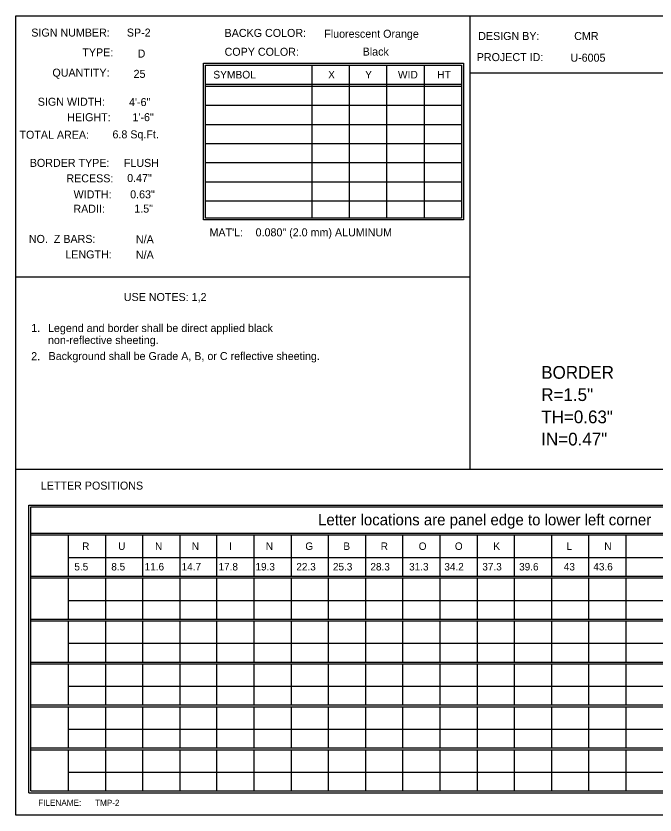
# Model space of a CAD drawing. Extents: x 766449 to 768137, y 650958 to 652521.
# Drawn here: x 767381.7 to 767770.1, y 651768.8 to 652254.2 of the extents above; entities that cross this region are included whole.
import ezdxf

# ---------------------------------------------------------------- set-up
doc = ezdxf.new("R2010")
doc.units = 0
doc.layers.add('Old_Level_3', color=7, linetype='Continuous')
doc.layers.add('Text', color=7, linetype='Continuous')

msp = doc.modelspace()

# ---------------------------------------------------------------- linework, layer by layer
at = {"layer": 'Text'}
for p, q in [((767657.51, 652254.24), (767657.51, 651978.93)), ((767561.46, 652224.37), (767561.46, 652131.49)), ((767584.2, 652224.37), (767584.2, 652131.49)), ((767606.95, 652224.37), (767606.95, 652131.49)), ((767629.69, 652224.37), (767629.69, 652131.49)), ((767657.51, 652219.7), (768081.66, 652219.7)), ((767496.83, 652212.76), (767652.43, 652212.76)), ((767496.83, 652211.61), (767652.43, 652211.61)), ((767496.83, 652200), (767652.43, 652200)), ((767496.83, 652188.39), (767652.43, 652188.39)), ((767496.83, 652176.78), (767652.43, 652176.78)), ((767496.83, 652165.17), (767652.43, 652165.17)), ((767496.83, 652153.56), (767652.43, 652153.56)), ((767496.83, 652141.95), (767652.43, 652141.95)), ((767657.51, 652095.65), (767381.66, 652095.65)), ((767381.66, 651978.93), (767657.51, 651978.93)), ((767657.51, 651978.93), (768081.66, 651978.93)), ((767390.64, 651940.06), (767928.82, 651940.06)), ((767390.64, 651938.93), (767928.82, 651938.93)), ((767413.33, 651938.93), (767413.33, 651913.95)), ((767436.02, 651938.93), (767436.02, 651913.95)), ((767458.48, 651938.93), (767458.48, 651913.95)), ((767481.18, 651938.93), (767481.18, 651913.95)), ((767503.64, 651938.93), (767503.64, 651913.95)), ((767526.33, 651938.93), (767526.33, 651913.95)), ((767549.02, 651938.93), (767549.02, 651913.95)), ((767571.48, 651938.93), (767571.48, 651913.95)), ((767594.18, 651938.93), (767594.18, 651913.95)), ((767616.64, 651938.93), (767616.64, 651913.95)), ((767639.33, 651938.93), (767639.33, 651913.95)), ((767662.02, 651938.93), (767662.02, 651913.95)), ((767684.48, 651938.93), (767684.48, 651913.95)), ((767707.18, 651938.93), (767707.18, 651913.95)), ((767729.64, 651938.93), (767729.64, 651913.95)), ((767752.33, 651938.93), (767752.33, 651913.95)), ((767413.33, 651925.3), (767928.82, 651925.3)), ((767390.64, 651913.95), (767928.82, 651913.95)), ((767390.64, 651912.82), (767928.82, 651912.82)), ((767413.33, 651912.82), (767413.33, 651887.85)), ((767436.02, 651912.82), (767436.02, 651887.85)), ((767458.48, 651912.82), (767458.48, 651887.85)), ((767481.18, 651912.82), (767481.18, 651887.85)), ((767503.64, 651912.82), (767503.64, 651887.85)), ((767526.33, 651912.82), (767526.33, 651887.85)), ((767549.02, 651912.82), (767549.02, 651887.85)), ((767571.48, 651912.82), (767571.48, 651887.85)), ((767594.18, 651912.82), (767594.18, 651887.85)), ((767616.64, 651912.82), (767616.64, 651887.85)), ((767639.33, 651912.82), (767639.33, 651887.85)), ((767662.02, 651912.82), (767662.02, 651887.85)), ((767684.48, 651912.82), (767684.48, 651887.85)), ((767707.18, 651912.82), (767707.18, 651887.85)), ((767729.64, 651912.82), (767729.64, 651887.85)), ((767752.33, 651912.82), (767752.33, 651887.85)), ((767413.33, 651899.2), (767928.82, 651899.2)), ((767390.64, 651887.85), (767928.82, 651887.85)), ((767390.64, 651886.71), (767928.82, 651886.71)), ((767413.33, 651886.71), (767413.33, 651861.74)), ((767436.02, 651886.71), (767436.02, 651861.74)), ((767458.48, 651886.71), (767458.48, 651861.74)), ((767481.18, 651886.71), (767481.18, 651861.74)), ((767503.64, 651886.71), (767503.64, 651861.74)), ((767526.33, 651886.71), (767526.33, 651861.74)), ((767549.02, 651886.71), (767549.02, 651861.74)), ((767571.48, 651886.71), (767571.48, 651861.74)), ((767594.18, 651886.71), (767594.18, 651861.74)), ((767616.64, 651886.71), (767616.64, 651861.74)), ((767639.33, 651886.71), (767639.33, 651861.74)), ((767662.02, 651886.71), (767662.02, 651861.74)), ((767684.48, 651886.71), (767684.48, 651861.74)), ((767707.18, 651886.71), (767707.18, 651861.74)), ((767729.64, 651886.71), (767729.64, 651861.74)), ((767752.33, 651886.71), (767752.33, 651861.74)), ((767413.33, 651873.09), (767928.82, 651873.09)), ((767390.64, 651861.74), (767928.82, 651861.74)), ((767390.64, 651860.61), (767928.82, 651860.61)), ((767413.33, 651860.61), (767413.33, 651835.63)), ((767436.02, 651860.61), (767436.02, 651835.63)), ((767458.48, 651860.61), (767458.48, 651835.63)), ((767481.18, 651860.61), (767481.18, 651835.63)), ((767503.64, 651860.61), (767503.64, 651835.63)), ((767526.33, 651860.61), (767526.33, 651835.63)), ((767549.02, 651860.61), (767549.02, 651835.63)), ((767571.48, 651860.61), (767571.48, 651835.63)), ((767594.18, 651860.61), (767594.18, 651835.63)), ((767616.64, 651860.61), (767616.64, 651835.63)), ((767639.33, 651860.61), (767639.33, 651835.63)), ((767662.02, 651860.61), (767662.02, 651835.63)), ((767684.48, 651860.61), (767684.48, 651835.63)), ((767707.18, 651860.61), (767707.18, 651835.63)), ((767729.64, 651860.61), (767729.64, 651835.63)), ((767752.33, 651860.61), (767752.33, 651835.63)), ((767413.33, 651846.98), (767928.82, 651846.98)), ((767413.33, 651838.54), (767413.33, 651835.63)), ((767436.02, 651838.54), (767436.02, 651835.63)), ((767458.48, 651838.54), (767458.48, 651835.63)), ((767481.18, 651838.54), (767481.18, 651835.63)), ((767503.64, 651838.54), (767503.64, 651835.63)), ((767526.33, 651838.54), (767526.33, 651835.63)), ((767549.02, 651838.54), (767549.02, 651835.63)), ((767571.48, 651838.54), (767571.48, 651835.63)), ((767594.18, 651838.54), (767594.18, 651835.63)), ((767616.64, 651838.54), (767616.64, 651835.63)), ((767639.33, 651838.54), (767639.33, 651835.63)), ((767662.02, 651838.54), (767662.02, 651835.63)), ((767684.48, 651838.54), (767684.48, 651835.63)), ((767707.18, 651838.54), (767707.18, 651835.63)), ((767729.64, 651838.54), (767729.64, 651835.63)), ((767752.33, 651838.54), (767752.33, 651835.63)), ((767390.64, 651835.63), (767928.82, 651835.63)), ((767390.64, 651835.63), (767928.82, 651835.63)), ((767390.64, 651834.5), (767928.82, 651834.5)), ((767390.64, 651834.5), (767928.82, 651834.5)), ((767413.33, 651834.5), (767413.33, 651811.16)), ((767413.33, 651834.5), (767413.33, 651809.53)), ((767436.02, 651834.5), (767436.02, 651811.16)), ((767436.02, 651834.5), (767436.02, 651809.53)), ((767458.48, 651834.5), (767458.48, 651811.16)), ((767458.48, 651834.5), (767458.48, 651809.53)), ((767481.18, 651834.5), (767481.18, 651811.16)), ((767481.18, 651834.5), (767481.18, 651809.53)), ((767503.64, 651834.5), (767503.64, 651811.16)), ((767503.64, 651834.5), (767503.64, 651809.53)), ((767526.33, 651834.5), (767526.33, 651811.16)), ((767526.33, 651834.5), (767526.33, 651809.53)), ((767549.02, 651834.5), (767549.02, 651811.16)), ((767549.02, 651834.5), (767549.02, 651809.53)), ((767571.48, 651834.5), (767571.48, 651811.16)), ((767571.48, 651834.5), (767571.48, 651809.53)), ((767594.18, 651834.5), (767594.18, 651811.16)), ((767594.18, 651834.5), (767594.18, 651809.53)), ((767616.64, 651834.5), (767616.64, 651811.16)), ((767616.64, 651834.5), (767616.64, 651809.53)), ((767639.33, 651834.5), (767639.33, 651811.16)), ((767639.33, 651834.5), (767639.33, 651809.53)), ((767662.02, 651834.5), (767662.02, 651811.16)), ((767662.02, 651834.5), (767662.02, 651809.53)), ((767684.48, 651834.5), (767684.48, 651811.16)), ((767684.48, 651834.5), (767684.48, 651809.53)), ((767707.18, 651834.5), (767707.18, 651811.16)), ((767707.18, 651834.5), (767707.18, 651809.53)), ((767729.64, 651834.5), (767729.64, 651811.16)), ((767729.64, 651834.5), (767729.64, 651809.53)), ((767752.33, 651834.5), (767752.33, 651811.16)), ((767752.33, 651834.5), (767752.33, 651809.53)), ((767413.33, 651820.88), (767928.82, 651820.88)), ((767413.33, 651820.88), (767928.82, 651820.88)), ((767390.64, 651809.53), (767928.82, 651809.53)), ((767390.64, 651809.53), (767928.82, 651809.53)), ((767390.64, 651808.39), (767928.82, 651808.39)), ((767390.64, 651808.39), (767928.82, 651808.39)), ((767413.33, 651812.43), (767413.33, 651809.53)), ((767413.33, 651808.39), (767413.33, 651783.42)), ((767413.33, 651808.39), (767413.33, 651783.42)), ((767436.02, 651812.43), (767436.02, 651809.53)), ((767436.02, 651808.39), (767436.02, 651783.42)), ((767436.02, 651808.39), (767436.02, 651783.42)), ((767458.48, 651812.43), (767458.48, 651809.53)), ((767458.48, 651808.39), (767458.48, 651783.42)), ((767458.48, 651808.39), (767458.48, 651783.42)), ((767481.18, 651812.43), (767481.18, 651809.53)), ((767481.18, 651808.39), (767481.18, 651783.42)), ((767481.18, 651808.39), (767481.18, 651783.42)), ((767503.64, 651812.43), (767503.64, 651809.53)), ((767503.64, 651808.39), (767503.64, 651783.42)), ((767503.64, 651808.39), (767503.64, 651783.42)), ((767526.33, 651812.43), (767526.33, 651809.53)), ((767526.33, 651808.39), (767526.33, 651783.42)), ((767526.33, 651808.39), (767526.33, 651783.42)), ((767549.02, 651812.43), (767549.02, 651809.53)), ((767549.02, 651808.39), (767549.02, 651783.42)), ((767549.02, 651808.39), (767549.02, 651783.42)), ((767571.48, 651812.43), (767571.48, 651809.53)), ((767571.48, 651808.39), (767571.48, 651783.42)), ((767571.48, 651808.39), (767571.48, 651783.42)), ((767594.18, 651812.43), (767594.18, 651809.53)), ((767594.18, 651808.39), (767594.18, 651783.42)), ((767594.18, 651808.39), (767594.18, 651783.42)), ((767616.64, 651812.43), (767616.64, 651809.53)), ((767616.64, 651808.39), (767616.64, 651783.42)), ((767616.64, 651808.39), (767616.64, 651783.42)), ((767639.33, 651812.43), (767639.33, 651809.53)), ((767639.33, 651808.39), (767639.33, 651783.42)), ((767639.33, 651808.39), (767639.33, 651783.42)), ((767662.02, 651812.43), (767662.02, 651809.53)), ((767662.02, 651808.39), (767662.02, 651783.42)), ((767662.02, 651808.39), (767662.02, 651783.42)), ((767684.48, 651812.43), (767684.48, 651809.53)), ((767684.48, 651808.39), (767684.48, 651783.42)), ((767684.48, 651808.39), (767684.48, 651783.42)), ((767707.18, 651812.43), (767707.18, 651809.53)), ((767707.18, 651808.39), (767707.18, 651783.42)), ((767707.18, 651808.39), (767707.18, 651783.42)), ((767729.64, 651812.43), (767729.64, 651809.53)), ((767729.64, 651808.39), (767729.64, 651783.42)), ((767729.64, 651808.39), (767729.64, 651783.42)), ((767752.33, 651812.43), (767752.33, 651809.53)), ((767752.33, 651808.39), (767752.33, 651783.42)), ((767752.33, 651808.39), (767752.33, 651783.42)), ((767413.33, 651794.77), (767928.82, 651794.77)), ((767413.33, 651794.77), (767928.82, 651794.77)), ((767389.48, 651782.29), (767928.82, 651782.29)), ((767390.64, 651783.42), (767928.82, 651783.42)), ((767390.64, 651783.42), (767928.82, 651783.42)), ((767390.64, 651782.29), (767928.82, 651782.29))]:
    msp.add_line(p, q, dxfattribs=at)
for points in [[(767381.66, 652254.24), (768081.66, 652254.24), (768081.66, 651768.77), (767381.66, 651768.77)], [(767495.64, 652225.54), (767653.62, 652225.54), (767653.62, 652130.34), (767495.64, 652130.34)], [(767496.83, 652224.37), (767652.43, 652224.37), (767652.43, 652131.49), (767496.83, 652131.49)]]:
    msp.add_lwpolyline(points, close=True, dxfattribs=at)
for points in [[(767389.48, 651811.16), (767389.48, 651957.09), (767928.82, 651957.09)], [(767390.64, 651811.16), (767390.64, 651955.95), (767928.82, 651955.95)], [(767389.48, 651782.29), (767389.48, 651838.54)], [(767390.64, 651783.42), (767390.64, 651838.54)]]:
    msp.add_lwpolyline(points, dxfattribs=at)

# ---------------------------------------------------------------- texts
at = {"layer": 'Old_Level_3'}
for s, height, p in [('SP-2', 4.865, (767449.04, 652241.72)), ('Fluorescent Orange', 4.8646, (767569.05, 652241.01)), ('D', 4.86, (767455.61, 652228.97)), ('25', 4.865, (767453.15, 652216.65)), ('4\'-6"', 4.865, (767450.37, 652199.5)), ('1\'-6"', 4.865, (767452.45, 652190.32)), ('6.8 Sq.Ft.', 4.865, (767440.32, 652179.89)), ('FLUSH', 4.865, (767447.24, 652162.54)), ('0.47"', 4.865, (767449.25, 652153.37)), ('0.63"', 4.865, (767451.07, 652143.43)), ('1.5"', 4.865, (767453.57, 652134.76)), ('N/A', 4.865, (767454.57, 652116.16)), ('N/A', 4.865, (767454.57, 652106.73))]:
    msp.add_text(s, height=height, rotation=360, dxfattribs=at).set_placement(p)
msp.add_text('Black', height=4.865, dxfattribs=at).set_placement((767592.39, 652230.16))
at = {"layer": 'Text'}
for s, height, p in [('SIGN NUMBER:', 4.8646, (767390.98, 652241.72)), ('BACKG COLOR:', 4.8646, (767508.47, 652241.51)), ('DESIGN BY:', 4.865, (767662.64, 652239.65)), ('COPY COLOR:', 4.8646, (767508.47, 652230.06)), ('TYPE:', 4.865, (767421.99, 652229.71)), ('PROJECT ID:', 4.8646, (767661.74, 652226.82)), ('U-6005', 4.865, (767718.66, 652226.47)), ('QUANTITY:', 4.865, (767403.82, 652217.38)), ('SIGN WIDTH:', 4.8646, (767394.93, 652199.7)), ('HEIGHT:', 4.865, (767412.83, 652190.3)), ('TOTAL AREA:', 4.8646, (767383.78, 652179.66)), ('BORDER TYPE:', 4.8646, (767390.06, 652162.56)), ('RECESS:', 4.865, (767412.31, 652153.16)), ('WIDTH:', 4.865, (767416.68, 652143.43)), ('RADII:', 4.865, (767416.57, 652134.68)), ("MAT'L:", 4.865, (767499.3, 652120.34)), ('NO.  Z BARS:', 4.8646, (767389.49, 652116.35)), ('LENGTH:', 4.865, (767411.66, 652106.95)), ('USE NOTES: 1,2', 4.8646, (767447.23, 652081.05)), ('1.', 4.865, (767390.93, 652062.22)), ('Legend and border shall be direct applied black      ', 4.8646, (767401.13, 652062.22)), ('2.', 4.865, (767390.93, 652045.12)), ('LETTER POSITIONS', 4.8646, (767396.78, 651966.48)), ('Letter locations are panel edge to lower left corner', 6.8105, (767565.29, 651944.78)), ('FILENAME:', 3.7, (767395.22, 651774.35))]:
    msp.add_text(s, height=height, rotation=360, dxfattribs=at).set_placement(p)
for s, height, p in [('CMR', 4.865, (767720.98, 652239.65)), ('SYMBOL', 4.644, (767501.62, 652216.26)), ('X', 4.64, (767571.4, 652216.26)), ('Y', 4.64, (767593.9, 652216.26)), ('WID', 4.644, (767613.84, 652216.26)), ('HT', 4.644, (767637.71, 652216.26)), ('0.080" (2.0 mm) ALUMINUM', 4.8646, (767527.33, 652120.34)), ('non-reflective sheeting.', 4.8646, (767401.13, 652054.92)), ('Background shall be Grade A, B, or C reflective sheeting.', 4.8646, (767401.48, 652045.2)), ('BORDER', 7.723, (767700.95, 652033.84)), ('R=1.5"', 7.723, (767700.95, 652020.32)), ('TH=0.63"', 7.723, (767700.95, 652006.81)), ('IN=0.47"', 7.723, (767700.95, 651993.29)), ('R', 4.54, (767421.9, 651929.85)), ('U', 4.54, (767443.8, 651929.85)), ('N', 4.54, (767466.18, 651929.85)), ('N', 4.54, (767488.55, 651929.85)), ('I', 4.54, (767511.2, 651929.85)), ('N', 4.54, (767533.55, 651929.85)), ('G', 4.54, (767557.56, 651929.85)), ('B', 4.54, (767580.7, 651929.85)), ('R', 4.54, (767603.39, 651929.85)), ('O', 4.54, (767626.47, 651929.85)), ('O', 4.54, (767648.45, 651929.85)), ('K', 4.54, (767671.83, 651929.85)), ('L', 4.54, (767716.34, 651929.85)), ('N', 4.54, (767739.29, 651929.85)), ('5.5', 4.54, (767417.16, 651917.36)), ('8.5', 4.54, (767439.61, 651917.36)), ('11.6', 4.54, (767459.88, 651917.36)), ('14.7', 4.54, (767482.35, 651917.36)), ('17.8', 4.54, (767504.78, 651917.36)), ('19.3', 4.54, (767527.24, 651917.36)), ('22.3', 4.54, (767552.08, 651917.36)), ('25.3', 4.54, (767574.33, 651917.36)), ('28.3', 4.54, (767597.11, 651917.36)), ('31.3', 4.54, (767620.63, 651917.36)), ('34.2', 4.54, (767642.04, 651917.36)), ('37.3', 4.54, (767665.13, 651917.36)), ('39.6', 4.54, (767687.51, 651917.36)), ('43', 4.54, (767714.66, 651917.36)), ('43.6', 4.54, (767732.61, 651917.36)), ('TMP-2', 3.7, (767429.75, 651774.35))]:
    msp.add_text(s, height=height, dxfattribs=at).set_placement(p)

doc.saveas('drawing.dxf')
